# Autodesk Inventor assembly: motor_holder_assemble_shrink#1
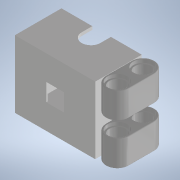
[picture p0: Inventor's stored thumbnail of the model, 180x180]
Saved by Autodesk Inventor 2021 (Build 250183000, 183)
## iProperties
Created: 2024-05
Part Number: motor_holder_assemble_shrink#1
Document SubType Name: Assembly
Designer: 23adrdam
Author: 23adrdam
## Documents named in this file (3)
- C:\Users\23adrdam\Desktop\driverbot\driverbot-adrian\models\motor_holder_assemble_shrink#1.iam
- C:\Users\23adrdam\Desktop\driverbot\driverbot-adrian\models\motor_holder#1.ipt
- C:\Users\23adrdam\Desktop\driverbot\driverbot-adrian\models\Imported Components\BEAM 2_\BEAM 2_.ipt
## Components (3 placed, 2 different names)
1. motor_holder#1:1 — Mate:1, Mate:2, Mate:4, Mate:5
2. BEAM 2_:1 — Mate:2, Mate:3, Mate:4
3. BEAM 2_:2 — Mate:1, Mate:3, Mate:5
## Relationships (5: Mate 5)
- Mate:1: motor_holder#1:1 ↔ BEAM 2_:2
- Mate:2: motor_holder#1:1 ↔ BEAM 2_:1
- Mate:3: BEAM 2_:1 ↔ BEAM 2_:2
- Mate:4: motor_holder#1:1 ↔ BEAM 2_:1
- Mate:5: motor_holder#1:1 ↔ BEAM 2_:2
